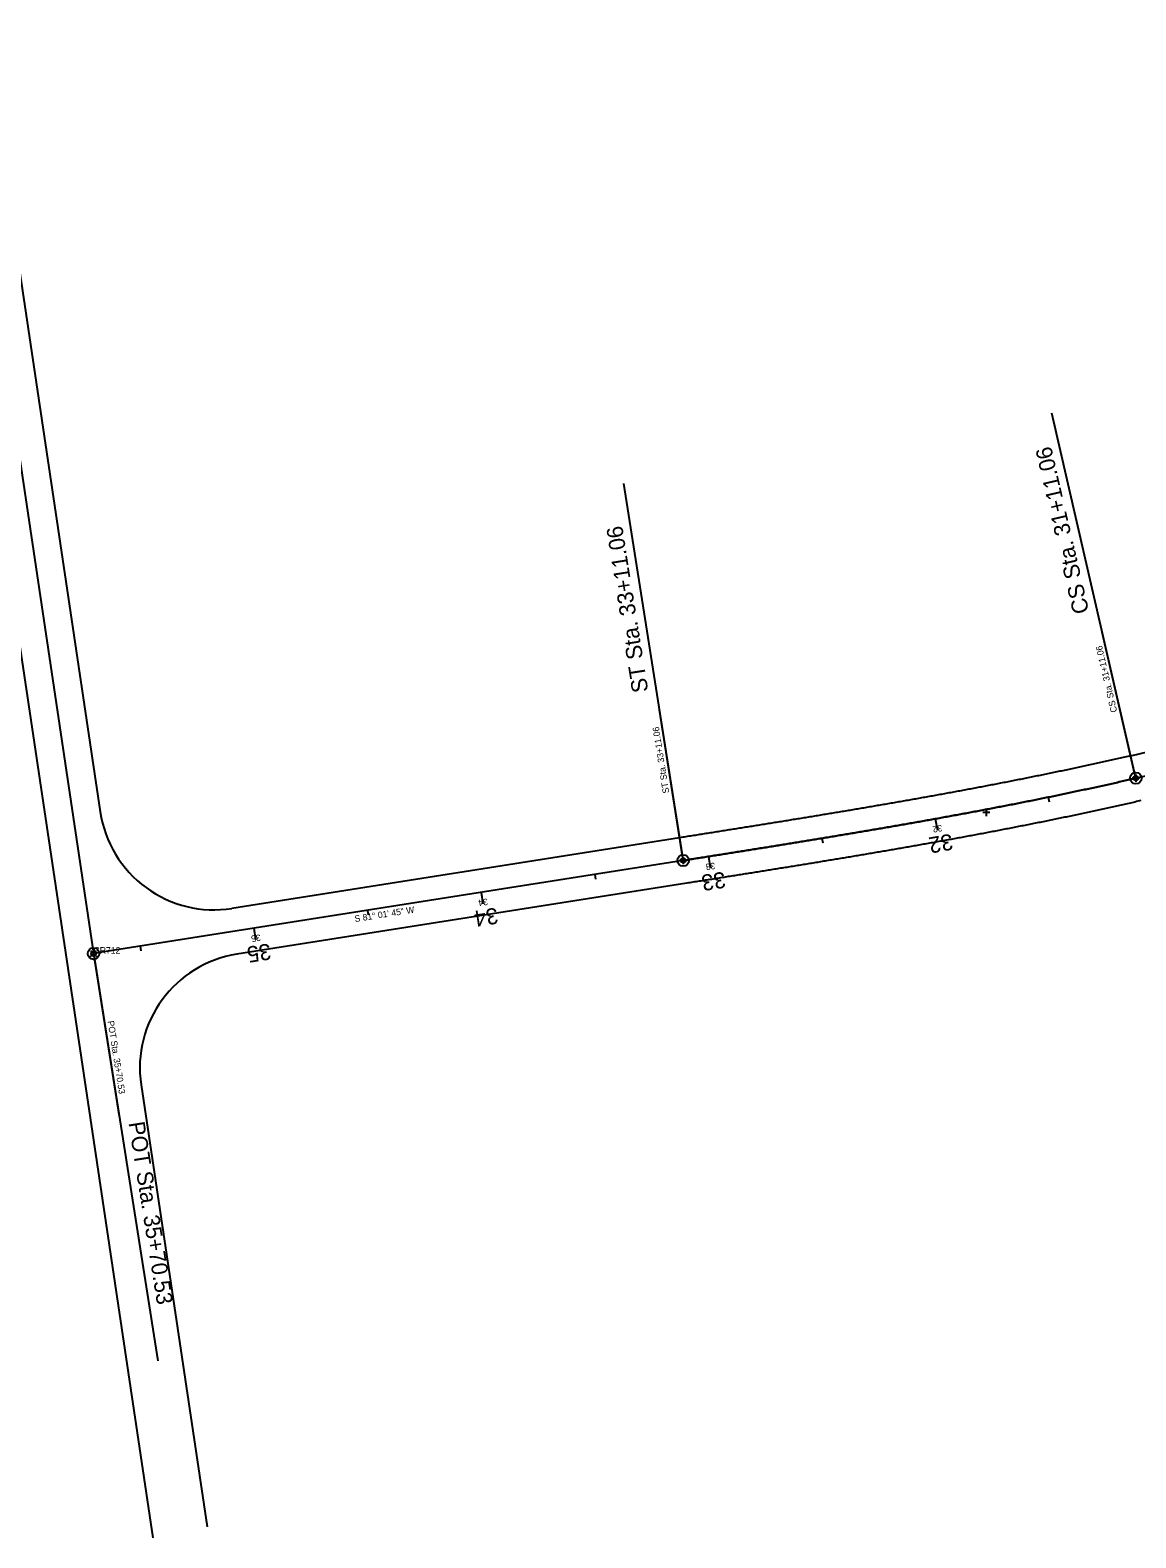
# Model space of a CAD drawing. Extents: x 6334 to 41599, y 9030 to 59113.
# Drawn here: x 22118 to 22599, y 27259 to 27915 of the extents above; entities that cross this region are included whole.
import ezdxf

# ---------------------------------------------------------------- set-up
doc = ezdxf.new("R2010")
doc.units = 0
for name, color, linetype in [('GE_X_CL_20', 7, 'Continuous'), ('GE_X_CL_50', 7, 'Continuous'), ('GK_Visualization', 7, 'Continuous'), ('PM_X_CL_Double_Solid', 7, 'Continuous'), ('PV_X_EOP', 7, 'Continuous')]:
    doc.layers.add(name, color=color, linetype=linetype)

msp = doc.modelspace()

# ---------------------------------------------------------------- linework, layer by layer
at = {"layer": 'GE_X_CL_20'}
for p, q in [((22598.86, 27590.57), (22584.47, 27653.06)), ((22402.2, 27554.82), (22392.01, 27619.36)), ((22561.04, 27581.34), (22561.44, 27579.38)), ((22511.93, 27571.94), (22512.28, 27569.97)), ((22462.65, 27563.48), (22462.97, 27561.51)), ((22402.36, 27553.83), (22146.06, 27513.37)), ((22413.28, 27555.56), (22413.59, 27553.58)), ((22363.89, 27547.76), (22364.21, 27545.78)), ((22314.5, 27539.96), (22314.82, 27537.99)), ((22265.12, 27532.17), (22265.43, 27530.19)), ((22215.73, 27524.37), (22216.04, 27522.4)), ((22166.34, 27516.57), (22166.65, 27514.6)), ((22146.21, 27512.38), (22157.23, 27442.6))]:
    msp.add_line(p, q, dxfattribs=at)
for centre in [(22599.09, 27589.6), (22402.36, 27553.83), (22146.06, 27513.37)]:
    msp.add_circle(centre, 1, dxfattribs=at)
msp.add_arc((22277.58, 28985.45), 1432.39, 282.97083, 293.32083, dxfattribs=at)
msp.add_spline([(22402.36, 27553.83), (22405.03, 27554.25), (22407.7, 27554.68), (22410.37, 27555.1), (22413.04, 27555.52), (22415.7, 27555.94), (22418.37, 27556.36), (22421.04, 27556.79), (22423.71, 27557.21), (22426.38, 27557.63), (22429.05, 27558.06), (22431.72, 27558.48), (22434.39, 27558.91), (22437.06, 27559.34), (22439.73, 27559.76), (22442.4, 27560.19), (22445.06, 27560.62), (22447.73, 27561.05), (22450.4, 27561.48), (22453.07, 27561.92), (22455.74, 27562.35), (22458.4, 27562.79), (22461.07, 27563.22), (22463.74, 27563.66), (22466.4, 27564.1), (22469.07, 27564.55), (22471.74, 27564.99), (22474.4, 27565.43), (22477.07, 27565.88), (22479.73, 27566.33), (22482.4, 27566.78), (22485.06, 27567.23), (22487.73, 27567.69), (22490.39, 27568.15), (22493.05, 27568.61), (22495.72, 27569.07), (22498.38, 27569.53), (22501.04, 27570), (22503.7, 27570.47), (22506.36, 27570.94), (22509.02, 27571.42), (22511.68, 27571.89), (22514.34, 27572.37), (22517, 27572.86), (22519.66, 27573.34), (22522.32, 27573.83), (22524.98, 27574.32), (22527.63, 27574.82), (22530.29, 27575.31), (22532.95, 27575.82), (22535.6, 27576.32), (22538.26, 27576.83), (22540.91, 27577.34), (22543.56, 27577.85), (22546.22, 27578.37), (22548.87, 27578.9), (22551.52, 27579.42), (22554.17, 27579.95), (22556.82, 27580.48), (22559.47, 27581.02), (22562.11, 27581.56), (22564.76, 27582.11), (22567.41, 27582.66), (22570.05, 27583.21), (22572.7, 27583.77), (22575.34, 27584.33), (22577.98, 27584.9), (22580.63, 27585.47), (22583.27, 27586.05), (22585.91, 27586.63), (22588.54, 27587.21), (22591.18, 27587.8), (22593.82, 27588.4), (22596.45, 27589), (22599.09, 27589.6)], degree=3, dxfattribs=at)
at = {"layer": 'GE_X_CL_50'}
for p, q in [((22598.53, 27592.04), (22562.55, 27748.25)), ((22401.97, 27556.3), (22376.5, 27717.64)), ((22511.93, 27571.94), (22512.81, 27567.02)), ((22402.36, 27553.83), (22146.06, 27513.37)), ((22413.28, 27555.56), (22414.06, 27550.62)), ((22314.5, 27539.96), (22315.28, 27535.02)), ((22215.73, 27524.37), (22216.51, 27519.43)), ((22146.45, 27510.9), (22173.99, 27336.43))]:
    msp.add_line(p, q, dxfattribs=at)
for centre in [(22599.09, 27589.6), (22402.36, 27553.83), (22146.06, 27513.37)]:
    msp.add_circle(centre, 2.5, dxfattribs=at)
msp.add_arc((22277.58, 28985.45), 1432.39, 282.97083, 293.32083, dxfattribs=at)
msp.add_spline([(22599.09, 27589.6), (22596.45, 27589), (22593.82, 27588.4), (22591.18, 27587.8), (22588.54, 27587.21), (22585.91, 27586.63), (22583.27, 27586.05), (22580.63, 27585.47), (22577.98, 27584.9), (22575.34, 27584.33), (22572.7, 27583.77), (22570.05, 27583.21), (22567.41, 27582.66), (22564.76, 27582.11), (22562.11, 27581.56), (22559.47, 27581.02), (22556.82, 27580.48), (22554.17, 27579.95), (22551.52, 27579.42), (22548.87, 27578.9), (22546.22, 27578.37), (22543.56, 27577.85), (22540.91, 27577.34), (22538.26, 27576.83), (22535.6, 27576.32), (22532.95, 27575.82), (22530.29, 27575.31), (22527.63, 27574.82), (22524.98, 27574.32), (22522.32, 27573.83), (22519.66, 27573.34), (22517, 27572.86), (22514.34, 27572.37), (22511.68, 27571.89), (22509.02, 27571.42), (22506.36, 27570.94), (22503.7, 27570.47), (22501.04, 27570), (22498.38, 27569.53), (22495.72, 27569.07), (22493.05, 27568.61), (22490.39, 27568.15), (22487.73, 27567.69), (22485.06, 27567.23), (22482.4, 27566.78), (22479.73, 27566.33), (22477.07, 27565.88), (22474.4, 27565.43), (22471.74, 27564.99), (22469.07, 27564.55), (22466.4, 27564.1), (22463.74, 27563.66), (22461.07, 27563.22), (22458.4, 27562.79), (22455.74, 27562.35), (22453.07, 27561.92), (22450.4, 27561.48), (22447.73, 27561.05), (22445.06, 27560.62), (22442.4, 27560.19), (22439.73, 27559.76), (22437.06, 27559.34), (22434.39, 27558.91), (22431.72, 27558.48), (22429.05, 27558.06), (22426.38, 27557.63), (22423.71, 27557.21), (22421.04, 27556.79), (22418.37, 27556.36), (22415.7, 27555.94), (22413.04, 27555.52), (22410.37, 27555.1), (22407.7, 27554.68), (22405.03, 27554.25), (22402.36, 27553.83)], degree=3, dxfattribs=at)
at = {"layer": 'GK_Visualization'}
for p, q in [((22600.65, 27589.6), (22597.53, 27589.6)), ((22600.65, 27589.6), (22597.53, 27589.6)), ((22599.09, 27591.16), (22599.09, 27588.04)), ((22599.09, 27591.16), (22599.09, 27588.04)), ((22535.65, 27574.63), (22532.53, 27574.63)), ((22534.09, 27576.19), (22534.09, 27573.07)), ((22402.36, 27553.83), (22146.06, 27513.37)), ((22403.92, 27553.83), (22400.8, 27553.83)), ((22402.36, 27555.39), (22402.36, 27552.27)), ((22144.73, 27512.04), (22147.39, 27514.71)), ((22144.73, 27514.71), (22147.39, 27512.04))]:
    msp.add_line(p, q, dxfattribs=at)
msp.add_arc((22277.58, 28985.45), 1432.39, 282.97083, 293.32083, dxfattribs=at)
msp.add_arc((22277.58, 28985.45), 1432.39, 282.97083, 293.32083, dxfattribs=at)
msp.add_spline([(22599.09, 27589.6), (22596.45, 27589), (22593.82, 27588.4), (22591.18, 27587.8), (22588.54, 27587.21), (22585.91, 27586.63), (22583.27, 27586.05), (22580.63, 27585.47), (22577.98, 27584.9), (22575.34, 27584.33), (22572.7, 27583.77), (22570.05, 27583.21), (22567.41, 27582.66), (22564.76, 27582.11), (22562.11, 27581.56), (22559.47, 27581.02), (22556.82, 27580.48), (22554.17, 27579.95), (22551.52, 27579.42), (22548.87, 27578.9), (22546.22, 27578.37), (22543.56, 27577.85), (22540.91, 27577.34), (22538.26, 27576.83), (22535.6, 27576.32), (22532.95, 27575.82), (22530.29, 27575.31), (22527.63, 27574.82), (22524.98, 27574.32), (22522.32, 27573.83), (22519.66, 27573.34), (22517, 27572.86), (22514.34, 27572.37), (22511.68, 27571.89), (22509.02, 27571.42), (22506.36, 27570.94), (22503.7, 27570.47), (22501.04, 27570), (22498.38, 27569.53), (22495.72, 27569.07), (22493.05, 27568.61), (22490.39, 27568.15), (22487.73, 27567.69), (22485.06, 27567.23), (22482.4, 27566.78), (22479.73, 27566.33), (22477.07, 27565.88), (22474.4, 27565.43), (22471.74, 27564.99), (22469.07, 27564.55), (22466.4, 27564.1), (22463.74, 27563.66), (22461.07, 27563.22), (22458.4, 27562.79), (22455.74, 27562.35), (22453.07, 27561.92), (22450.4, 27561.48), (22447.73, 27561.05), (22445.06, 27560.62), (22442.4, 27560.19), (22439.73, 27559.76), (22437.06, 27559.34), (22434.39, 27558.91), (22431.72, 27558.48), (22429.05, 27558.06), (22426.38, 27557.63), (22423.71, 27557.21), (22421.04, 27556.79), (22418.37, 27556.36), (22415.7, 27555.94), (22413.04, 27555.52), (22410.37, 27555.1), (22407.7, 27554.68), (22405.03, 27554.25), (22402.36, 27553.83)], degree=3, dxfattribs=at)
msp.add_spline([(22599.09, 27589.6), (22596.45, 27589), (22593.82, 27588.4), (22591.18, 27587.8), (22588.54, 27587.21), (22585.91, 27586.63), (22583.27, 27586.05), (22580.63, 27585.47), (22577.98, 27584.9), (22575.34, 27584.33), (22572.7, 27583.77), (22570.05, 27583.21), (22567.41, 27582.66), (22564.76, 27582.11), (22562.11, 27581.56), (22559.47, 27581.02), (22556.82, 27580.48), (22554.17, 27579.95), (22551.52, 27579.42), (22548.87, 27578.9), (22546.22, 27578.37), (22543.56, 27577.85), (22540.91, 27577.34), (22538.26, 27576.83), (22535.6, 27576.32), (22532.95, 27575.82), (22530.29, 27575.31), (22527.63, 27574.82), (22524.98, 27574.32), (22522.32, 27573.83), (22519.66, 27573.34), (22517, 27572.86), (22514.34, 27572.37), (22511.68, 27571.89), (22509.02, 27571.42), (22506.36, 27570.94), (22503.7, 27570.47), (22501.04, 27570), (22498.38, 27569.53), (22495.72, 27569.07), (22493.05, 27568.61), (22490.39, 27568.15), (22487.73, 27567.69), (22485.06, 27567.23), (22482.4, 27566.78), (22479.73, 27566.33), (22477.07, 27565.88), (22474.4, 27565.43), (22471.74, 27564.99), (22469.07, 27564.55), (22466.4, 27564.1), (22463.74, 27563.66), (22461.07, 27563.22), (22458.4, 27562.79), (22455.74, 27562.35), (22453.07, 27561.92), (22450.4, 27561.48), (22447.73, 27561.05), (22445.06, 27560.62), (22442.4, 27560.19), (22439.73, 27559.76), (22437.06, 27559.34), (22434.39, 27558.91), (22431.72, 27558.48), (22429.05, 27558.06), (22426.38, 27557.63), (22423.71, 27557.21), (22421.04, 27556.79), (22418.37, 27556.36), (22415.7, 27555.94), (22413.04, 27555.52), (22410.37, 27555.1), (22407.7, 27554.68), (22405.03, 27554.25), (22402.36, 27553.83)], degree=3, dxfattribs=at)
at = {"layer": 'PM_X_CL_Double_Solid'}
msp.add_line((21262.51, 33423.7), (22146.06, 27513.37), dxfattribs=at)
at = {"layer": 'PV_X_EOP'}
for p, q in [((21274.38, 33425.48), (22148.98, 27574.99)), ((21250.65, 33421.93), (22171.88, 27259.45)), ((22400.8, 27563.71), (22206.23, 27532.99)), ((22403.92, 27543.95), (22208.38, 27513.09)), ((22166.72, 27456.31), (22195.43, 27264.25))]:
    msp.add_line(p, q, dxfattribs=at)
for centre, radius, start, end in [((22277.58, 28985.45), 1422.39, 282.97083, 293.32083), ((22198.43, 27582.38), 50, 188.50227, 278.97083), ((22216.17, 27463.7), 50, 98.97083, 188.50227)]:
    msp.add_arc(centre, radius, start, end, dxfattribs=at)
for points in [[(22596.85, 27599.35), (22594.23, 27598.74), (22591.61, 27598.15), (22588.99, 27597.56), (22586.37, 27596.97), (22583.75, 27596.39), (22581.13, 27595.82), (22578.5, 27595.24), (22575.88, 27594.68), (22573.25, 27594.11), (22570.63, 27593.55), (22568, 27593), (22565.37, 27592.45), (22562.74, 27591.9), (22560.1, 27591.36), (22557.47, 27590.82), (22554.84, 27590.29), (22552.2, 27589.76), (22549.57, 27589.23), (22546.93, 27588.71), (22544.29, 27588.19), (22541.65, 27587.67), (22539.01, 27587.16), (22536.37, 27586.65), (22533.73, 27586.14), (22531.09, 27585.64), (22528.44, 27585.14), (22525.8, 27584.65), (22523.15, 27584.15), (22520.51, 27583.66), (22517.86, 27583.18), (22515.21, 27582.69), (22512.56, 27582.21), (22509.91, 27581.73), (22507.26, 27581.26), (22504.61, 27580.79), (22501.96, 27580.32), (22499.31, 27579.85), (22496.66, 27579.38), (22494, 27578.92), (22491.35, 27578.46), (22488.69, 27578), (22486.04, 27577.55), (22483.38, 27577.09), (22480.72, 27576.64), (22478.07, 27576.19), (22475.41, 27575.74), (22472.75, 27575.3), (22470.09, 27574.85), (22467.43, 27574.41), (22464.77, 27573.97), (22462.11, 27573.53), (22459.45, 27573.09), (22456.79, 27572.66), (22454.13, 27572.22), (22451.46, 27571.79), (22448.8, 27571.36), (22446.14, 27570.92), (22443.47, 27570.49), (22440.81, 27570.07), (22438.14, 27569.64), (22435.48, 27569.21), (22432.81, 27568.78), (22430.15, 27568.36), (22427.48, 27567.93), (22424.81, 27567.51), (22422.15, 27567.09), (22419.48, 27566.66), (22416.81, 27566.24), (22414.14, 27565.82), (22411.47, 27565.4), (22408.81, 27564.97), (22406.14, 27564.55), (22403.47, 27564.13), (22400.8, 27563.71)], [(22601.32, 27579.85), (22598.68, 27579.25), (22596.03, 27578.64), (22593.37, 27578.04), (22590.72, 27577.45), (22588.06, 27576.86), (22585.41, 27576.28), (22582.75, 27575.7), (22580.09, 27575.12), (22577.43, 27574.55), (22574.77, 27573.99), (22572.11, 27573.43), (22569.45, 27572.87), (22566.79, 27572.32), (22564.13, 27571.77), (22561.46, 27571.22), (22558.8, 27570.68), (22556.14, 27570.15), (22553.47, 27569.61), (22550.81, 27569.09), (22548.14, 27568.56), (22545.48, 27568.04), (22542.81, 27567.52), (22540.14, 27567.01), (22537.48, 27566.5), (22534.81, 27565.99), (22532.14, 27565.49), (22529.47, 27564.99), (22526.8, 27564.49), (22524.13, 27564), (22521.46, 27563.5), (22518.79, 27563.02), (22516.12, 27562.53), (22513.45, 27562.05), (22510.78, 27561.57), (22508.11, 27561.1), (22505.44, 27560.62), (22502.77, 27560.15), (22500.1, 27559.68), (22497.43, 27559.22), (22494.76, 27558.75), (22492.09, 27558.29), (22489.41, 27557.83), (22486.74, 27557.38), (22484.07, 27556.92), (22481.4, 27556.47), (22478.72, 27556.02), (22476.05, 27555.57), (22473.38, 27555.13), (22470.71, 27554.68), (22468.04, 27554.24), (22465.36, 27553.8), (22462.69, 27553.36), (22460.02, 27552.92), (22457.35, 27552.48), (22454.67, 27552.05), (22452, 27551.61), (22449.33, 27551.18), (22446.66, 27550.75), (22443.98, 27550.32), (22441.31, 27549.89), (22438.64, 27549.46), (22435.97, 27549.03), (22433.3, 27548.61), (22430.62, 27548.18), (22427.95, 27547.76), (22425.28, 27547.33), (22422.61, 27546.91), (22419.94, 27546.49), (22417.27, 27546.06), (22414.6, 27545.64), (22411.93, 27545.22), (22409.26, 27544.8), (22406.59, 27544.38), (22403.92, 27543.95)]]:
    msp.add_spline(points, degree=3, dxfattribs=at)

# ---------------------------------------------------------------- texts
at = {"layer": 'GE_X_CL_20'}
for s, rotation, p in [('CS Sta. 31+11.06', 102.97083, (22590.99, 27618.52)), ('ST Sta. 33+11.06', 98.97083, (22396.3, 27583.25)), ('32', 190.20426, (22514.71, 27569.39)), ('33', 188.98307, (22416.04, 27552.96)), ('S 81%%d 01\' 45" W', 8.97083, (22259.75, 27527.07)), ('34', 188.97083, (22317.22, 27537.35)), ('35', 188.97083, (22218.47, 27521.77)), ('POT Sta. 35+70.53', 278.97083, (22152.12, 27483.96))]:
    msp.add_text(s, height=2.8, rotation=rotation, dxfattribs=at).set_placement(p)
at = {"layer": 'GE_X_CL_50'}
for s, rotation, p in [('CS Sta. 31+11.06', 102.97083, (22578.84, 27661.9)), ('ST Sta. 33+11.06', 98.97083, (22387.2, 27627.37)), ('32', 190.20426, (22518.87, 27565.57)), ('33', 188.98307, (22420.17, 27549.05)), ('34', 188.97083, (22321.28, 27533.44)), ('35', 188.97083, (22222.59, 27517.86)), ('POT Sta. 35+70.53', 278.97083, (22161.21, 27439.84))]:
    msp.add_text(s, height=7, rotation=rotation, dxfattribs=at).set_placement(p)
at = {"layer": 'GK_Visualization'}
msp.add_text('CR712', height=2.8, dxfattribs=at).set_placement((22146.06, 27513.37))

doc.saveas('drawing.dxf')
